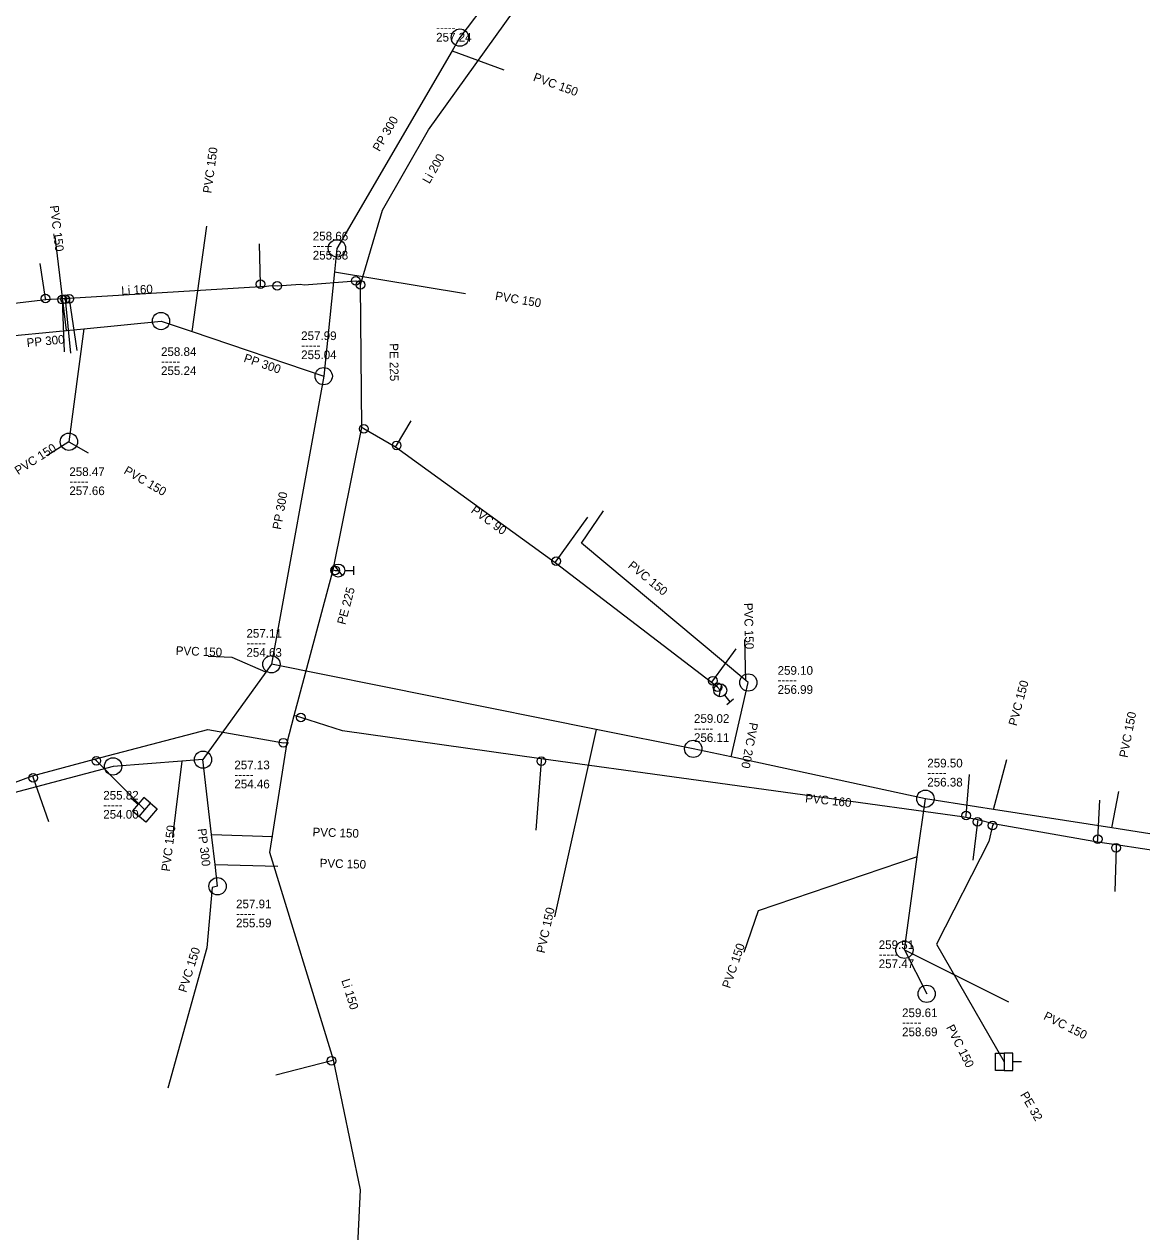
# Model space of a CAD drawing. Extents: x -770828 to -770111, y -1050344 to -1049447.
# Drawn here: x -770653 to -770523.9, y -1050055.5 to -1049916.1 of the extents above; entities that cross this region are included whole.
import ezdxf

# ---------------------------------------------------------------- set-up
doc = ezdxf.new("R2010")
doc.units = 0
doc.layers.add('Level 0', color=7, linetype='Continuous')

msp = doc.modelspace()

# ---------------------------------------------------------------- linework, layer by layer
at = {"layer": 'Level 0'}
for p, q in [((-770606.25, -1049928.29), (-770590.92, -1049906.89)), ((-770598, -1049911.45), (-770602.63, -1049917.64)), ((-770602.63, -1049917.64), (-770603.53, -1049919.18)), ((-770603.53, -1049919.18), (-770616.84, -1049941.97)), ((-770603.53, -1049919.18), (-770597.56, -1049921.34)), ((-770611.57, -1049937.55), (-770606.25, -1049928.29)), ((-770614.04, -1049945.91), (-770611.57, -1049937.55)), ((-770633.56, -1049951.58), (-770631.87, -1049939.4)), ((-770648.08, -1049951.45), (-770649.37, -1049940.61)), ((-770625.67, -1049946.11), (-770625.8, -1049941.44)), ((-770616.84, -1049941.97), (-770617.12, -1049944.68)), ((-770650.5, -1049947.75), (-770651.12, -1049943.73)), ((-770617.12, -1049944.68), (-770618.37, -1049956.73)), ((-770617.12, -1049944.68), (-770601.98, -1049947.19)), ((-770647.77, -1049947.71), (-770625.66, -1049946.38)), ((-770625.66, -1049946.38), (-770625.67, -1049946.11)), ((-770625.66, -1049946.38), (-770624.98, -1049946.34)), ((-770624.98, -1049946.34), (-770624.42, -1049946.27)), ((-770624.42, -1049946.27), (-770623.73, -1049946.29)), ((-770623.73, -1049946.29), (-770621.03, -1049946.11)), ((-770621.03, -1049946.11), (-770620.63, -1049946.19)), ((-770620.63, -1049946.19), (-770614.67, -1049945.73)), ((-770614.67, -1049945.73), (-770614.04, -1049945.91)), ((-770614.12, -1049946.17), (-770614.04, -1049945.91)), ((-770613.96, -1049962.67), (-770614.12, -1049946.17)), ((-770661, -1049949.12), (-770650.48, -1049947.87)), ((-770650.48, -1049947.87), (-770650.5, -1049947.75)), ((-770650.48, -1049947.87), (-770648.58, -1049947.76)), ((-770648.58, -1049947.76), (-770648.24, -1049947.74)), ((-770648.58, -1049947.76), (-770648.57, -1049947.89)), ((-770648.57, -1049947.89), (-770648.36, -1049953.91)), ((-770648.24, -1049947.74), (-770647.77, -1049947.71)), ((-770648.24, -1049947.74), (-770648.23, -1049947.83)), ((-770648.23, -1049947.83), (-770647.62, -1049954.09)), ((-770647.77, -1049947.71), (-770647.75, -1049947.81)), ((-770647.75, -1049947.81), (-770646.88, -1049953.78)), ((-770646.06, -1049951.25), (-770637.16, -1049950.36)), ((-770637.16, -1049950.36), (-770633.56, -1049951.58)), ((-770660.54, -1049952.69), (-770648.08, -1049951.45)), ((-770648.08, -1049951.45), (-770646.06, -1049951.25)), ((-770646.06, -1049951.25), (-770647.8, -1049964.3)), ((-770633.56, -1049951.58), (-770618.37, -1049956.73)), ((-770618.37, -1049956.73), (-770624.4, -1049989.99)), ((-770609.94, -1049964.72), (-770608.26, -1049961.89)), ((-770617.29, -1049979.08), (-770613.96, -1049962.67)), ((-770613.72, -1049962.81), (-770613.96, -1049962.67)), ((-770610.06, -1049964.93), (-770613.72, -1049962.81)), ((-770647.8, -1049964.3), (-770650.35, -1049965.93)), ((-770647.8, -1049964.3), (-770645.57, -1049965.6)), ((-770610.06, -1049964.93), (-770609.94, -1049964.72)), ((-770591.65, -1049978.28), (-770610.06, -1049964.93)), ((-770591.51, -1049978.08), (-770587.85, -1049973)), ((-770588.6, -1049976.01), (-770586.04, -1049972.28)), ((-770569.61, -1049991.86), (-770588.6, -1049976.01)), ((-770617.15, -1049978.58), (-770616.23, -1049979.76)), ((-770614.94, -1049978.67), (-770614.94, -1049979.67)), ((-770591.65, -1049978.28), (-770591.51, -1049978.08)), ((-770573.57, -1049992.1), (-770591.65, -1049978.28)), ((-770621.77, -1049995.92), (-770617.29, -1049979.08)), ((-770617.29, -1049979.08), (-770617.04, -1049979.15)), ((-770617.04, -1049979.15), (-770616.69, -1049979.17)), ((-770615.94, -1049979.17), (-770614.94, -1049979.17)), ((-770569.61, -1049991.86), (-770569.73, -1049987.13)), ((-770573.41, -1049991.89), (-770570.71, -1049988.23)), ((-770628.94, -1049989.21), (-770631.71, -1049989.11)), ((-770625.07, -1049990.92), (-770628.94, -1049989.21)), ((-770624.4, -1049989.99), (-770625.07, -1049990.92)), ((-770586.89, -1049997.51), (-770624.4, -1049989.99)), ((-770625.07, -1049990.92), (-770632.31, -1050001.01)), ((-770573.57, -1049992.1), (-770573.41, -1049991.89)), ((-770572.88, -1049992.63), (-770573.57, -1049992.1)), ((-770572.56, -1049993), (-770572.88, -1049992.63)), ((-770572.41, -1049992.27), (-770572.72, -1049993.74)), ((-770571.29, -1050000.7), (-770569.32, -1049992.1)), ((-770569.32, -1049992.1), (-770569.61, -1049991.86)), ((-770572.08, -1049993.57), (-770571.44, -1049994.34)), ((-770571.05, -1049994.02), (-770571.82, -1049994.66)), ((-770622.6, -1049999.04), (-770621.77, -1049995.92)), ((-770621, -1049996.13), (-770621.77, -1049995.92)), ((-770616.2, -1049997.69), (-770621, -1049996.13)), ((-770644.83, -1050000.94), (-770631.77, -1049997.52)), ((-770631.77, -1049997.52), (-770623.03, -1049999.05)), ((-770593.24, -1050000.93), (-770616.2, -1049997.69)), ((-770586.89, -1049997.51), (-770591.7, -1050019.14)), ((-770575.68, -1049999.76), (-770586.89, -1049997.51)), ((-770624.58, -1050011.72), (-770622.6, -1049999.04)), ((-770623.03, -1049999.05), (-770622.6, -1049999.04)), ((-770571.29, -1050000.7), (-770575.68, -1049999.76)), ((-770652.02, -1050002.86), (-770644.83, -1050000.94)), ((-770644.63, -1050001.14), (-770644.83, -1050000.94)), ((-770639.03, -1050006.8), (-770644.63, -1050001.14)), ((-770634.75, -1050001.19), (-770642.7, -1050001.79)), ((-770634.75, -1050001.19), (-770635.84, -1050009.91)), ((-770632.31, -1050001.01), (-770634.75, -1050001.19)), ((-770631.32, -1050009.65), (-770632.31, -1050001.01)), ((-770593.23, -1050001.19), (-770593.88, -1050009.16)), ((-770593.24, -1050000.93), (-770593.23, -1050001.19)), ((-770544.62, -1050007.62), (-770593.24, -1050000.93)), ((-770548.87, -1050005.52), (-770571.29, -1050000.7)), ((-770541.02, -1050006.75), (-770539.46, -1050001)), ((-770642.7, -1050001.79), (-770654.72, -1050005)), ((-770544.16, -1050007.45), (-770543.78, -1050002.72)), ((-770677.84, -1050012.6), (-770652.02, -1050002.86)), ((-770652.02, -1050002.86), (-770651.93, -1050003.1)), ((-770651.93, -1050003.1), (-770650.15, -1050008.15)), ((-770640.56, -1050005.51), (-770639.8, -1050006.16)), ((-770549.8, -1050012.23), (-770548.87, -1050005.52)), ((-770541.02, -1050006.75), (-770548.87, -1050005.52)), ((-770527.35, -1050008.9), (-770526.53, -1050004.67)), ((-770527.35, -1050008.9), (-770541.02, -1050006.75)), ((-770528.96, -1050010.19), (-770528.72, -1050005.7)), ((-770544.18, -1050007.7), (-770544.62, -1050007.62)), ((-770544.18, -1050007.7), (-770544.16, -1050007.45)), ((-770542.82, -1050007.96), (-770544.18, -1050007.7)), ((-770542.85, -1050008.19), (-770543.38, -1050012.6)), ((-770542.82, -1050007.96), (-770542.85, -1050008.19)), ((-770541.02, -1050008.43), (-770542.82, -1050007.96)), ((-770630.92, -1050013.1), (-770631.32, -1050009.65)), ((-770631.32, -1050009.65), (-770624.24, -1050009.89)), ((-770541.1, -1050008.61), (-770541.54, -1050010.45)), ((-770541.02, -1050008.43), (-770541.1, -1050008.61)), ((-770529.43, -1050010.45), (-770541.02, -1050008.43)), ((-770511.54, -1050011.38), (-770527.35, -1050008.9)), ((-770541.54, -1050010.45), (-770547.57, -1050022.33)), ((-770528.98, -1050010.52), (-770529.43, -1050010.45)), ((-770528.98, -1050010.52), (-770528.96, -1050010.19)), ((-770526.84, -1050010.84), (-770528.98, -1050010.52)), ((-770526.84, -1050010.84), (-770526.85, -1050011.19)), ((-770515.73, -1050012.51), (-770526.84, -1050010.84)), ((-770617.23, -1050035.68), (-770624.58, -1050011.72)), ((-770549.8, -1050012.23), (-770568.18, -1050018.47)), ((-770551.29, -1050022.97), (-770549.8, -1050012.23)), ((-770526.85, -1050011.19), (-770526.98, -1050016.25)), ((-770630.63, -1050015.63), (-770630.92, -1050013.1)), ((-770630.92, -1050013.1), (-770623.68, -1050013.31)), ((-770631.25, -1050015.79), (-770631.87, -1050022.72)), ((-770630.63, -1050015.63), (-770631.25, -1050015.79)), ((-770568.18, -1050018.47), (-770569.83, -1050023.26)), ((-770631.87, -1050022.72), (-770636.39, -1050038.95)), ((-770551.29, -1050022.97), (-770548.72, -1050028.05)), ((-770551.29, -1050022.97), (-770539.25, -1050028.99)), ((-770547.57, -1050022.33), (-770539.78, -1050035.91)), ((-770617.46, -1050035.77), (-770623.9, -1050037.43)), ((-770617.23, -1050035.68), (-770617.46, -1050035.77)), ((-770614.13, -1050050.69), (-770617.23, -1050035.68)), ((-770537.78, -1050035.91), (-770538.78, -1050035.91)), ((-770614.88, -1050067.15), (-770614.13, -1050050.69))]:
    msp.add_line(p, q, dxfattribs=at)
for points in [[(-770639.15, -1050005.39), (-770640.44, -1050006.92), (-770639.67, -1050007.57), (-770638.39, -1050006.03)], [(-770538.78, -1050036.91), (-770538.78, -1050034.91), (-770539.78, -1050034.91), (-770539.78, -1050036.91)]]:
    msp.add_lwpolyline(points, close=True, dxfattribs=at)
for points in [[(-770638.39, -1050006.03), (-770637.62, -1050006.68), (-770638.91, -1050008.21), (-770639.67, -1050007.57)], [(-770539.78, -1050036.91), (-770540.78, -1050036.91), (-770540.78, -1050034.91), (-770539.78, -1050034.91)]]:
    msp.add_lwpolyline(points, dxfattribs=at)
for centre, radius in [((-770602.63, -1049917.64), 1), ((-770616.84, -1049941.97), 1), ((-770614.67, -1049945.73), 0.5), ((-770625.67, -1049946.11), 0.5), ((-770623.73, -1049946.29), 0.5), ((-770614.12, -1049946.17), 0.5), ((-770650.5, -1049947.75), 0.5), ((-770648.57, -1049947.89), 0.5), ((-770648.23, -1049947.83), 0.5), ((-770647.75, -1049947.81), 0.5), ((-770637.16, -1049950.36), 1), ((-770618.37, -1049956.73), 1), ((-770613.72, -1049962.81), 0.5), ((-770647.8, -1049964.3), 1), ((-770609.94, -1049964.72), 0.5), ((-770591.51, -1049978.08), 0.5), ((-770617.04, -1049979.15), 0.5), ((-770616.69, -1049979.17), 0.75), ((-770624.4, -1049989.99), 1), ((-770573.41, -1049991.89), 0.5), ((-770569.32, -1049992.1), 1), ((-770572.88, -1049992.63), 0.5), ((-770572.56, -1049993), 0.75), ((-770621, -1049996.13), 0.5), ((-770623.03, -1049999.05), 0.5), ((-770575.68, -1049999.76), 1), ((-770644.63, -1050001.14), 0.5), ((-770642.7, -1050001.79), 1), ((-770632.31, -1050001.01), 1), ((-770593.23, -1050001.19), 0.5), ((-770651.93, -1050003.1), 0.5), ((-770548.87, -1050005.52), 1), ((-770544.16, -1050007.45), 0.5), ((-770542.85, -1050008.19), 0.5), ((-770541.1, -1050008.61), 0.5), ((-770528.96, -1050010.19), 0.5), ((-770526.85, -1050011.19), 0.5), ((-770630.63, -1050015.63), 1), ((-770551.29, -1050022.97), 1), ((-770548.72, -1050028.05), 1), ((-770617.46, -1050035.77), 0.5)]:
    msp.add_circle(centre, radius, dxfattribs=at)

# ---------------------------------------------------------------- texts
for s, p in [('-----', (-770605.38, -1049916.99)), ('257.24', (-770605.38, -1049918.09)), ('258.66', (-770619.63, -1049941.06)), ('-----', (-770619.63, -1049942.16)), ('255.88', (-770619.63, -1049943.26)), ('257.99', (-770620.97, -1049952.56)), ('258.84', (-770637.16, -1049954.4)), ('-----', (-770620.97, -1049953.66)), ('255.04', (-770620.97, -1049954.76)), ('-----', (-770637.16, -1049955.5)), ('255.24', (-770637.16, -1049956.6)), ('258.47', (-770647.75, -1049968.26)), ('-----', (-770647.75, -1049969.36)), ('257.66', (-770647.75, -1049970.46)), ('257.11', (-770627.29, -1049986.93)), ('-----', (-770627.29, -1049988.03)), ('254.63', (-770627.29, -1049989.13)), ('259.10', (-770565.94, -1049991.21)), ('-----', (-770565.94, -1049992.31)), ('256.99', (-770565.94, -1049993.41)), ('259.02', (-770575.6, -1049996.76)), ('-----', (-770575.6, -1049997.86)), ('256.11', (-770575.6, -1049998.96)), ('257.13', (-770628.69, -1050002.12)), ('259.50', (-770548.65, -1050001.91)), ('-----', (-770548.65, -1050003.01)), ('-----', (-770628.69, -1050003.22)), ('254.46', (-770628.69, -1050004.32)), ('256.38', (-770548.65, -1050004.11)), ('255.82', (-770643.83, -1050005.62)), ('-----', (-770643.83, -1050006.72)), ('254.00', (-770643.83, -1050007.82)), ('257.91', (-770628.49, -1050018.17)), ('-----', (-770628.49, -1050019.27)), ('255.59', (-770628.49, -1050020.37)), ('259.51', (-770554.26, -1050022.88)), ('-----', (-770554.26, -1050023.98)), ('257.47', (-770554.26, -1050025.08)), ('259.61', (-770551.56, -1050030.74)), ('-----', (-770551.56, -1050031.84)), ('258.69', (-770551.56, -1050032.94))]:
    msp.add_text(s, height=1, dxfattribs=at).set_placement(p)
for s, rotation, p in [('PVC 150', 340.109, (-770594.25, -1049922.6)), ('PP 300', 59.714, (-770611.92, -1049930.87)), ('PVC 150', 82.101, (-770631.35, -1049935.66)), ('Li 200', 60.122, (-770606.16, -1049934.59)), ('PVC 150', 276.786, (-770649.99, -1049937.07)), ('Li 160', 3.313, (-770641.72, -1049947.35)), ('PVC 150', 350.587, (-770598.62, -1049947.92)), ('PP 300', 5.654, (-770652.63, -1049953.38)), ('PE 225', 270.556, (-770610.76, -1049952.93)), ('PP 300', 341.279, (-770627.68, -1049955.05)), ('PVC 150', 32.587, (-770653.66, -1049968.16)), ('PVC 150', 329.76, (-770641.54, -1049967.91)), ('PP 300', 79.724, (-770623.32, -1049974.5)), ('PVC 90', 324.052, (-770601.44, -1049972.41)), ('PVC 150', 320.755, (-770583.3, -1049978.75)), ('PE 225', 75.102, (-770615.88, -1049985.49)), ('PVC 150', 271.453, (-770569.82, -1049982.92)), ('PVC 150', 357.932, (-770635.47, -1049988.91)), ('PVC 150', 74.821, (-770538.33, -1049997.18)), ('PVC 150', 79.029, (-770525.52, -1050000.84)), ('PVC 200', 259.428, (-770569.17, -1049996.65)), ('PVC 160', 354, (-770562.79, -1050005.93)), ('PVC 150', 82.875, (-770636.14, -1050013.96)), ('PP 300', 276.613, (-770632.93, -1050009.01)), ('PVC 150', 358.059, (-770619.67, -1050009.85)), ('PVC 150', 358.339, (-770618.84, -1050013.45)), ('PVC 150', 77.463, (-770592.84, -1050023.42)), ('PVC 150', 70.993, (-770571.44, -1050027.49)), ('PVC 150', 72.247, (-770634.24, -1050027.97)), ('Li 150', 287.054, (-770616.34, -1050026.49)), ('PVC 150', 333.435, (-770535.3, -1050030.94)), ('PVC 150', 296.835, (-770546.5, -1050031.91)), ('PE 32', 300, (-770537.95, -1050039.7))]:
    msp.add_text(s, height=1, rotation=rotation, dxfattribs=at).set_placement(p)

doc.saveas('drawing.dxf')
